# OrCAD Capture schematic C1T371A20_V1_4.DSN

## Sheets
1 000_Log: title: TELINK; rev: V1.4; note: C1T371A20
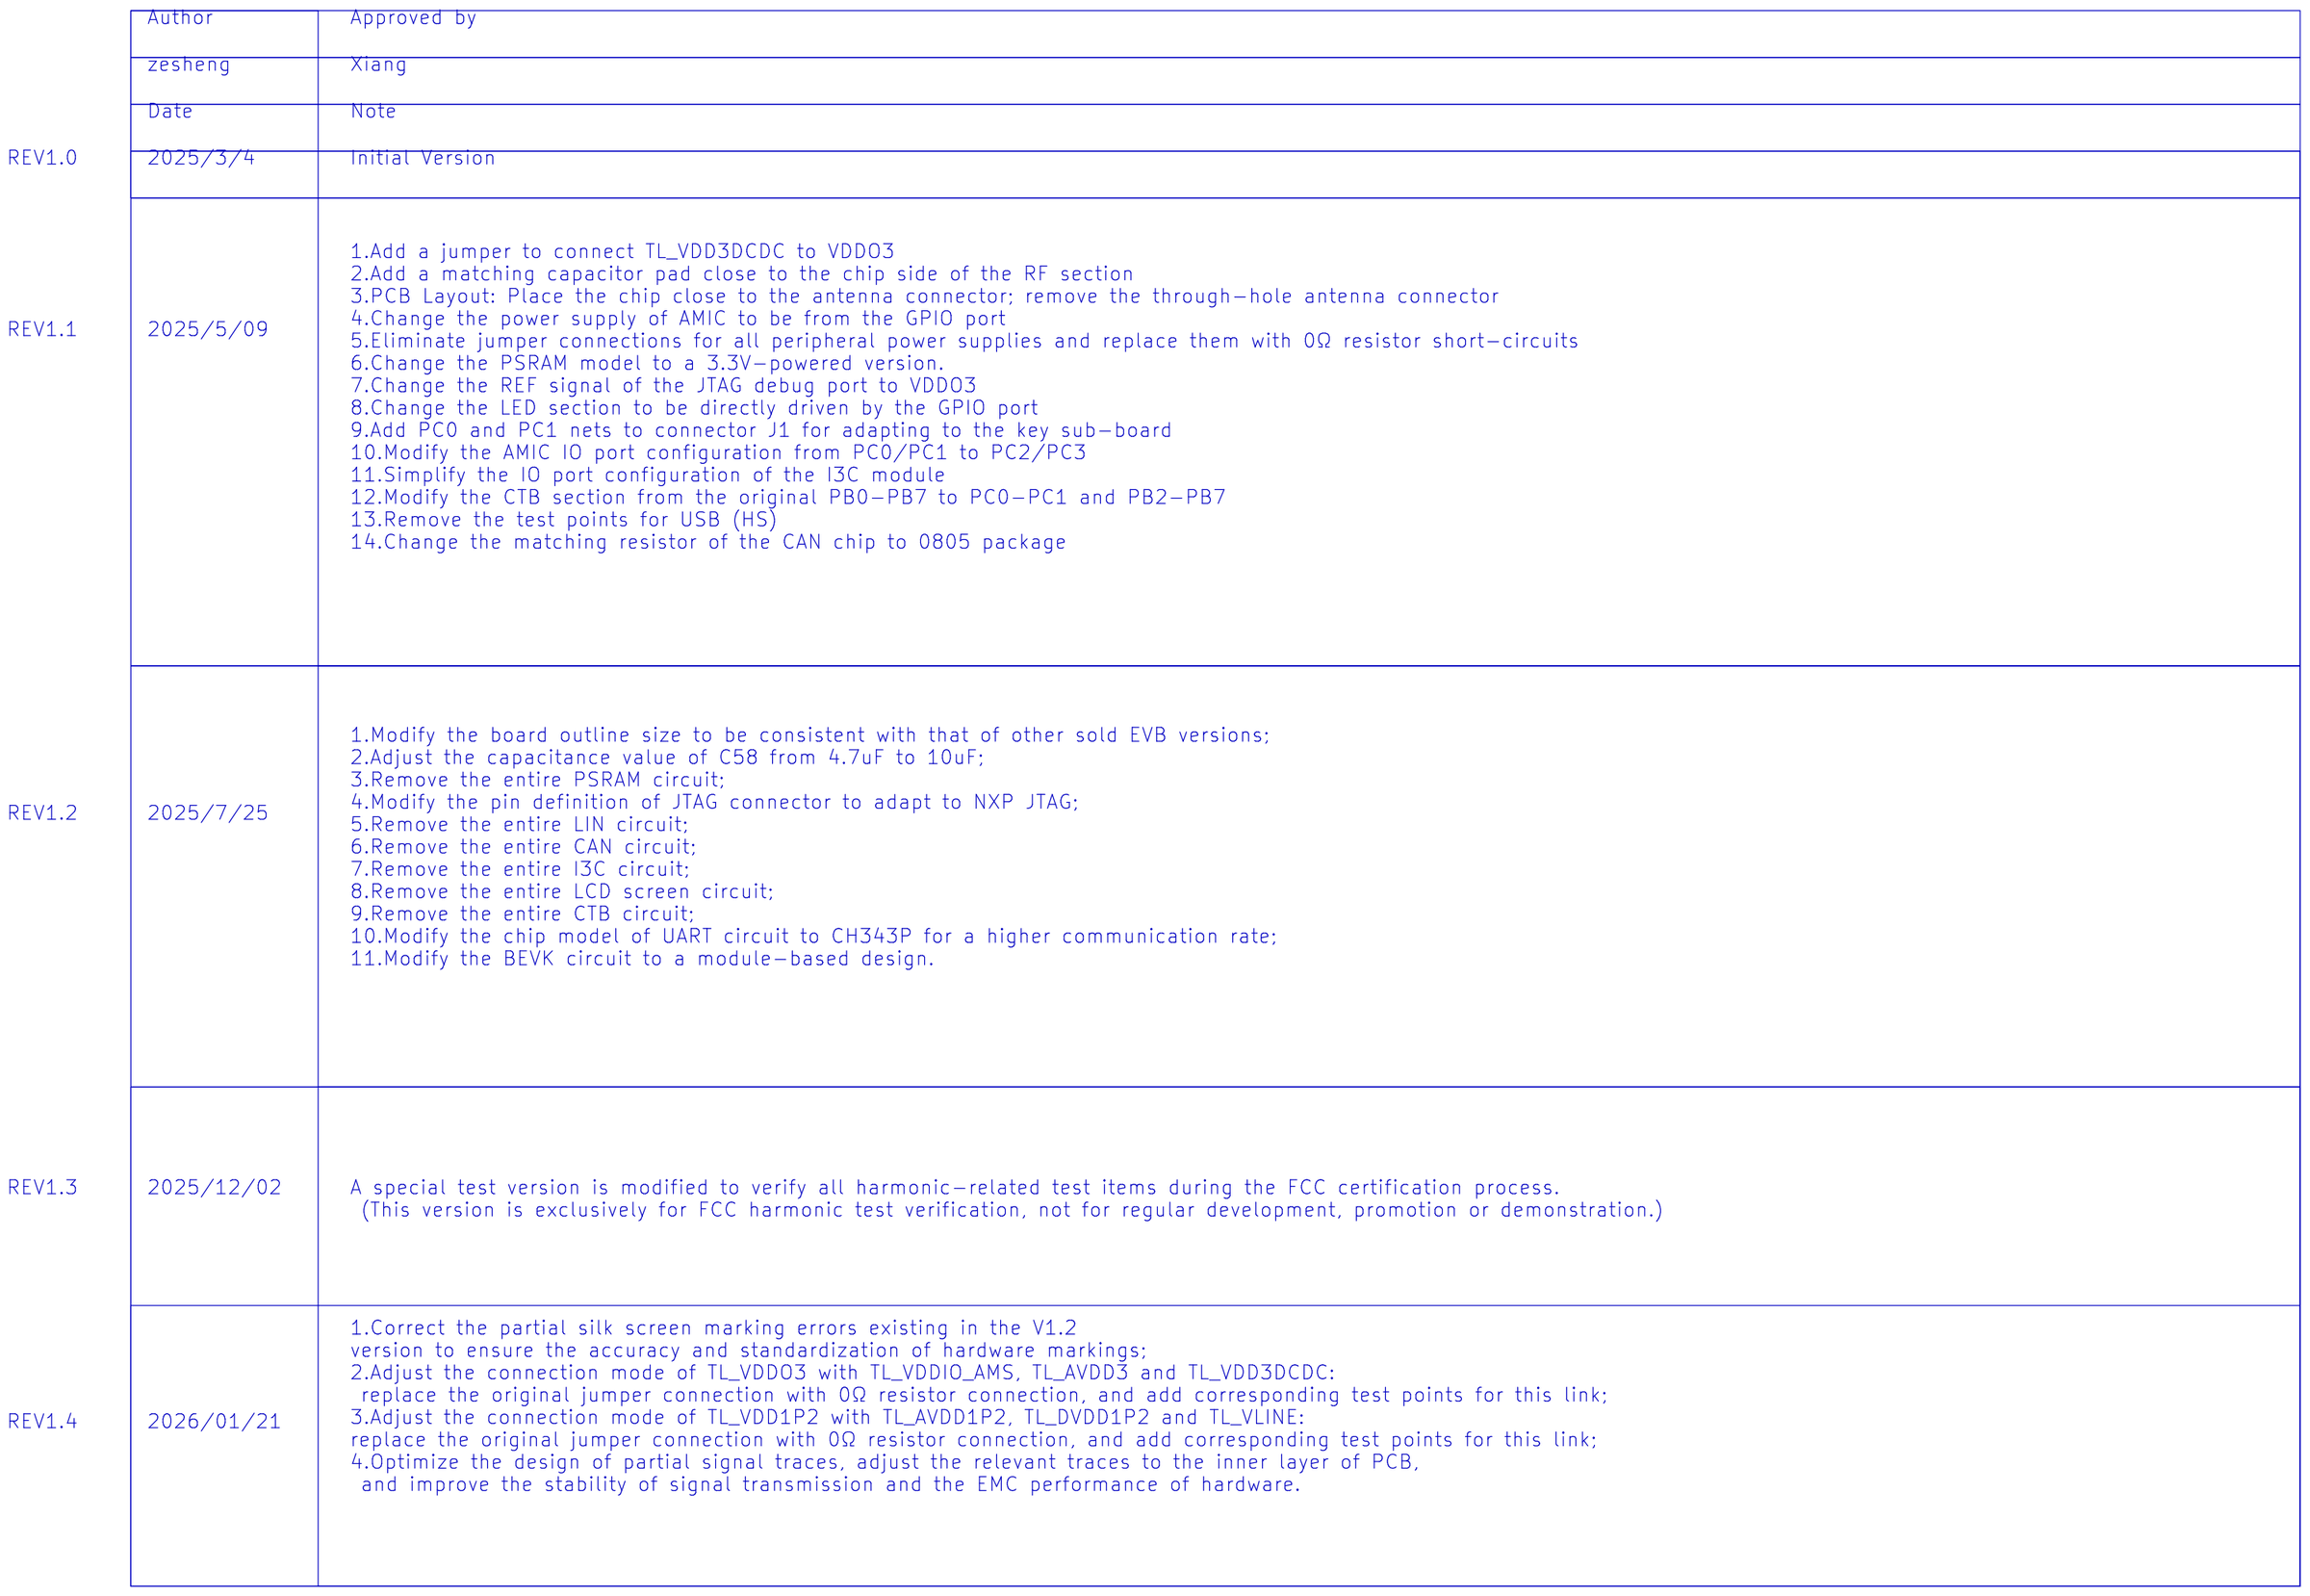
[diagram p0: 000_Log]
2 001_MAIN: size A3
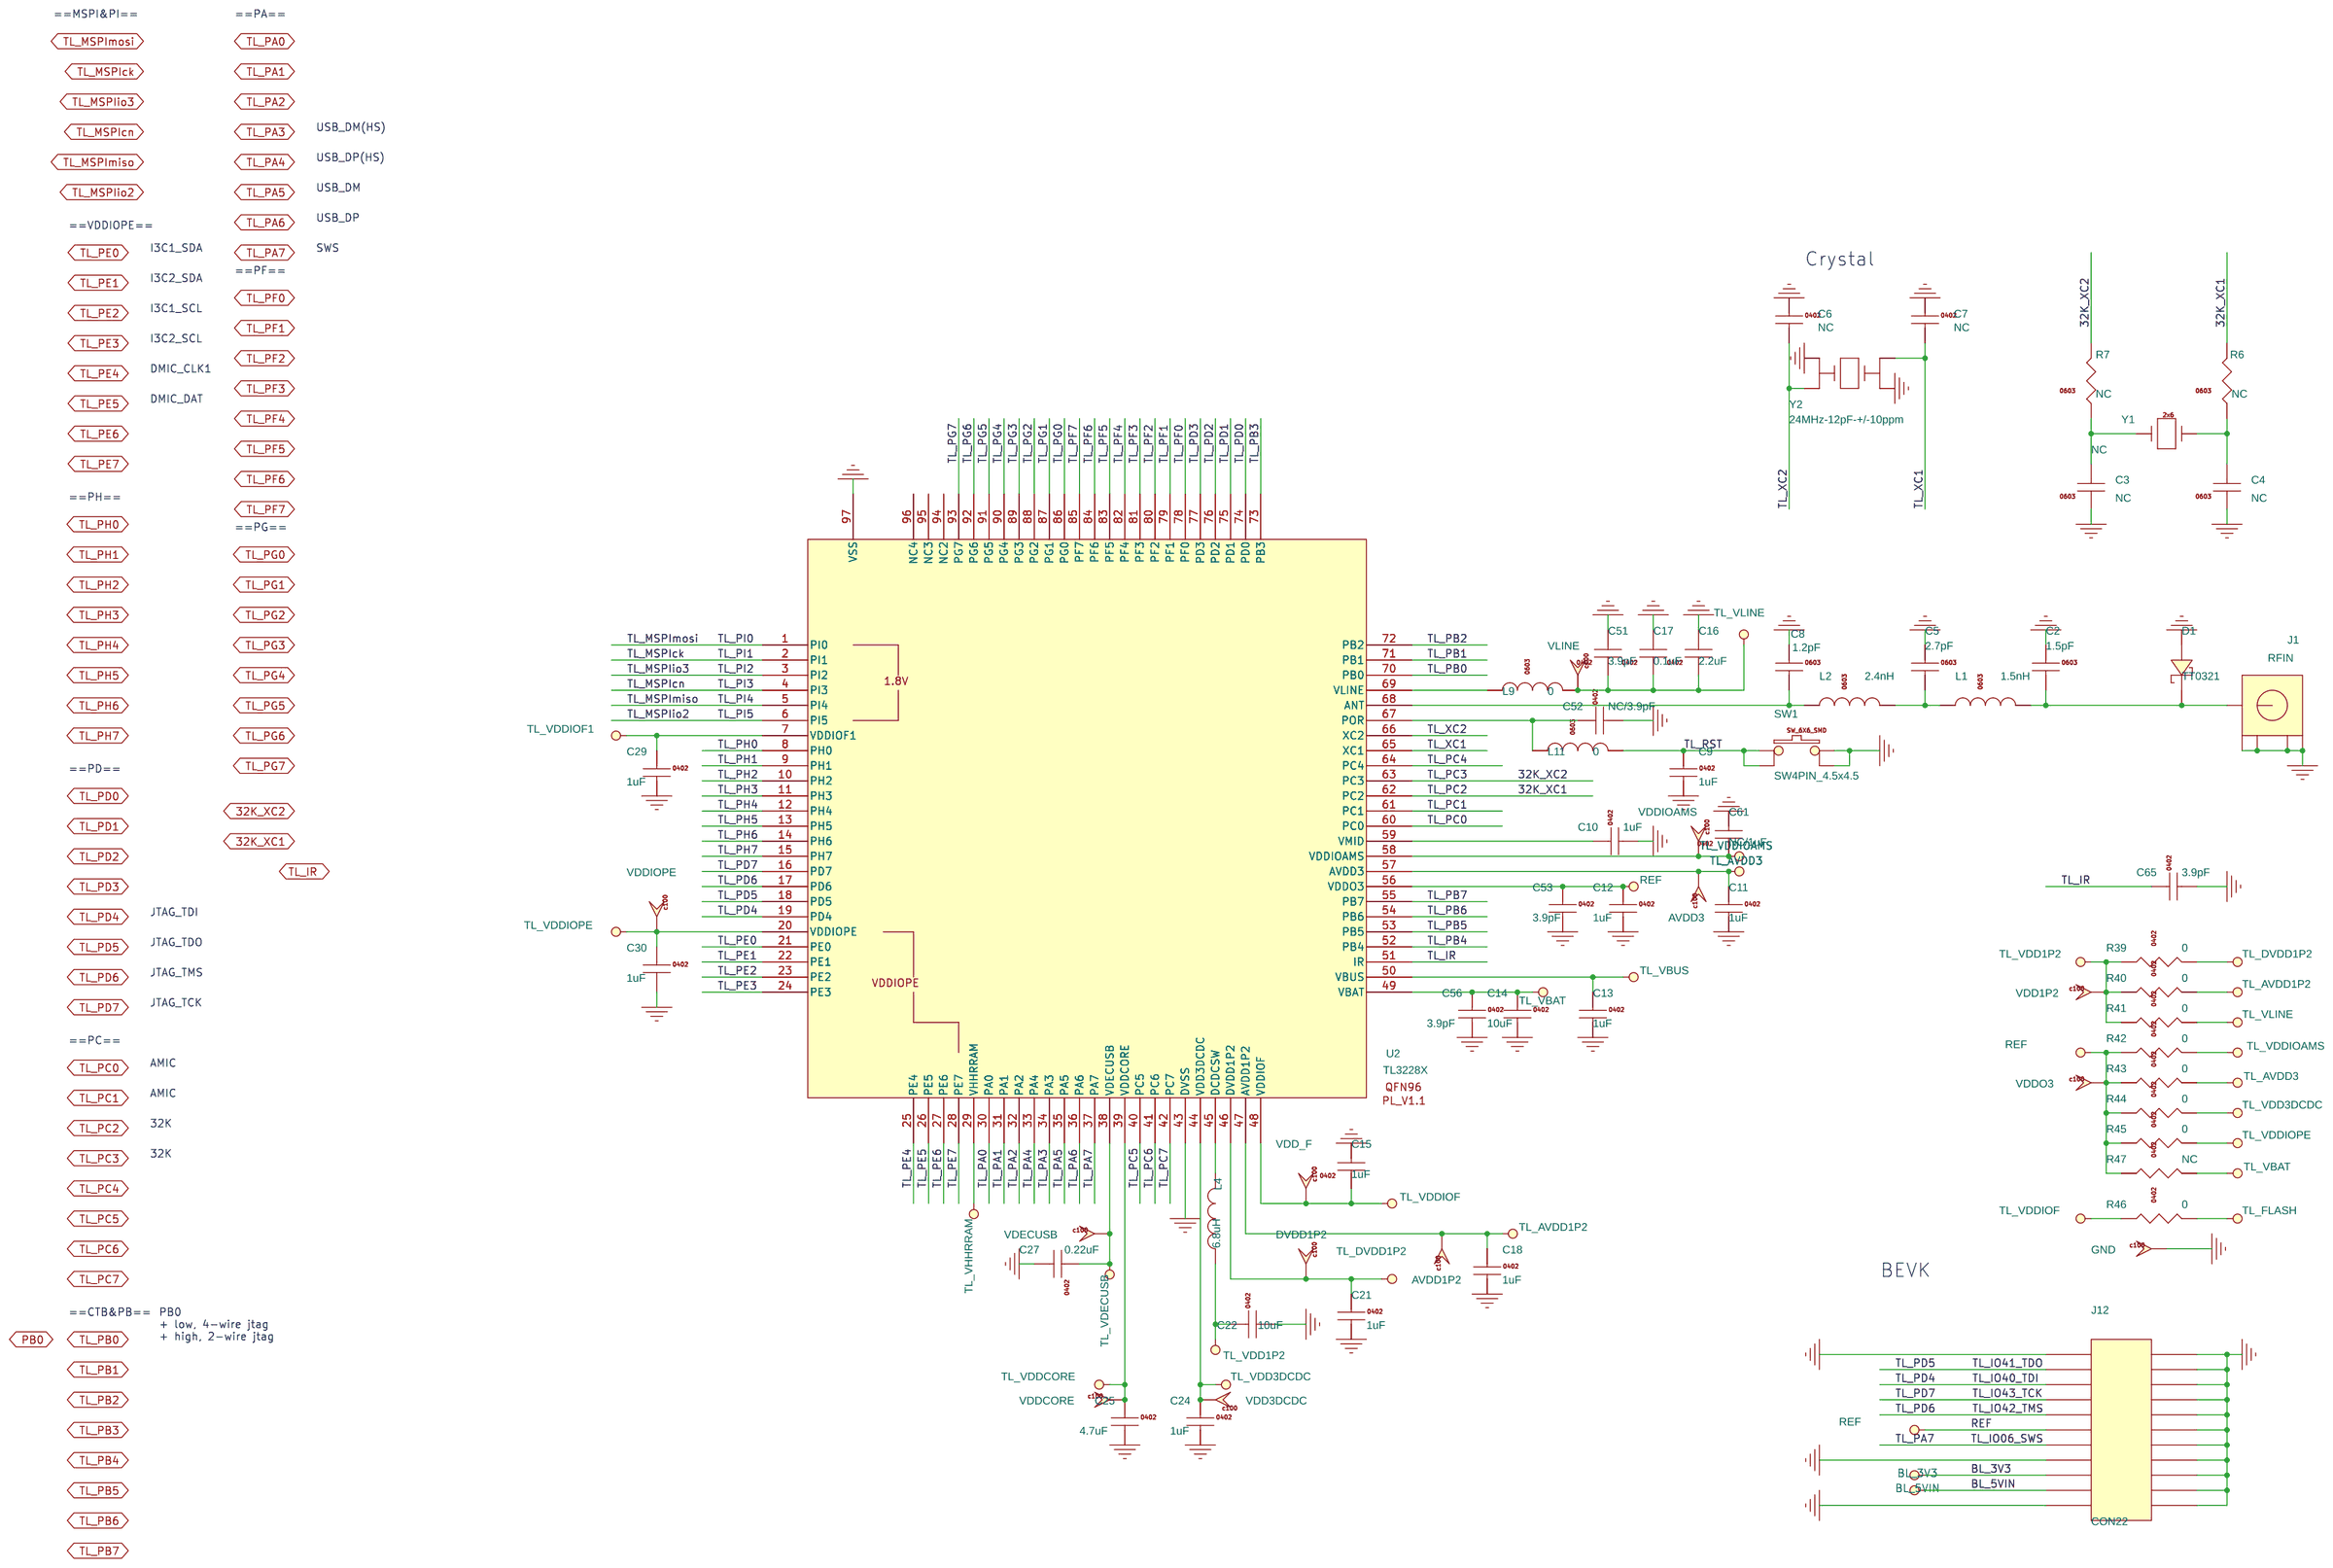
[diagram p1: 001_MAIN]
3 002_AUDIO: size A3
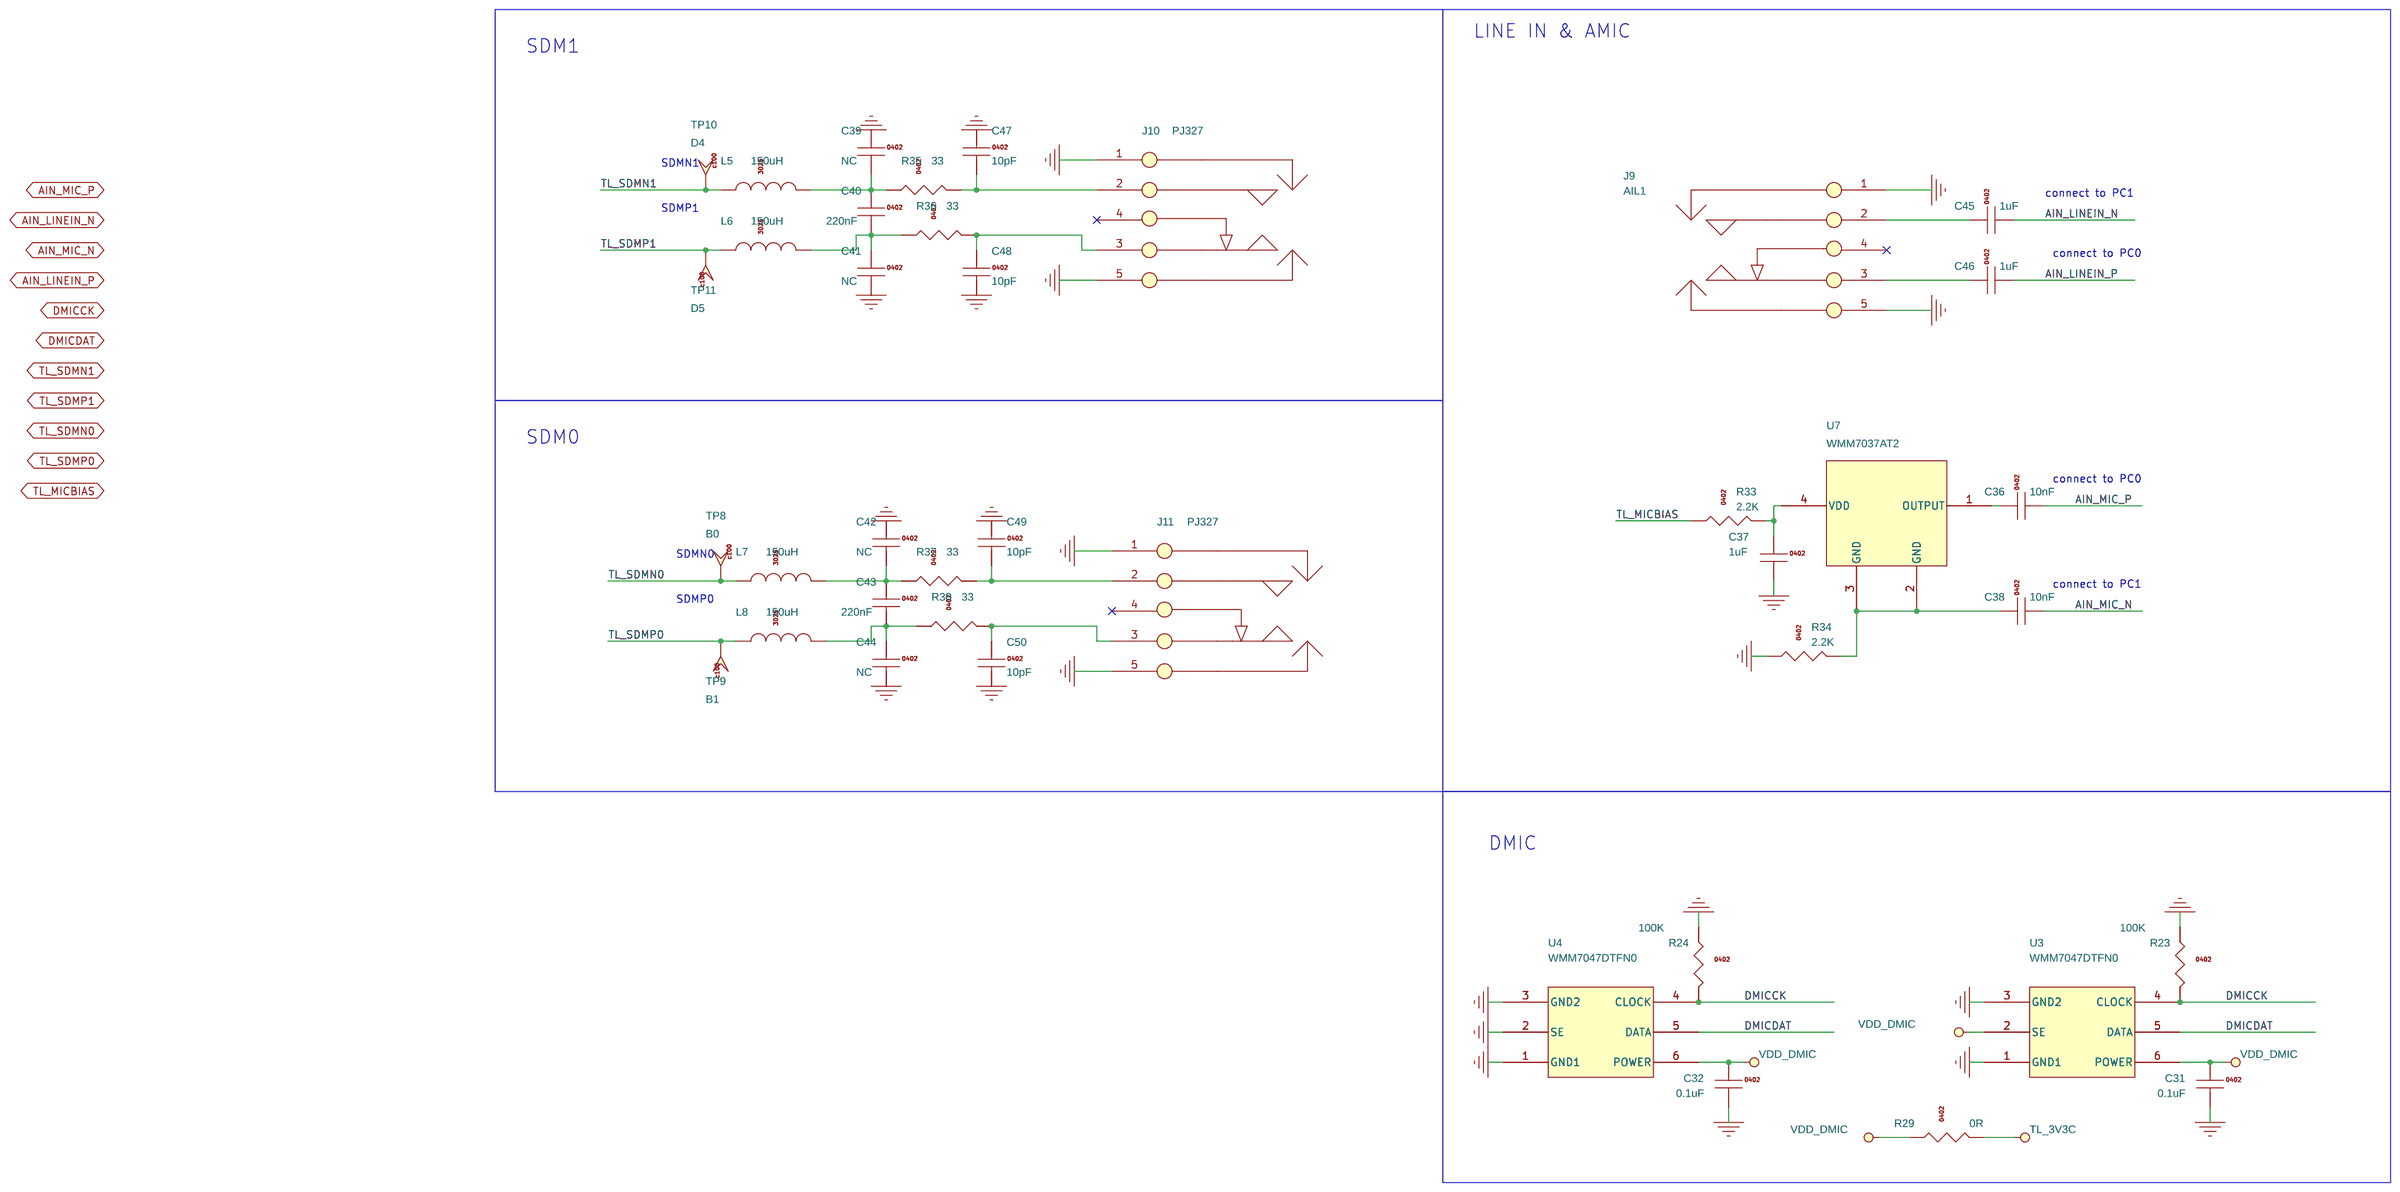
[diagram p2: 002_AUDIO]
4 003_INTERFACE1: size A3
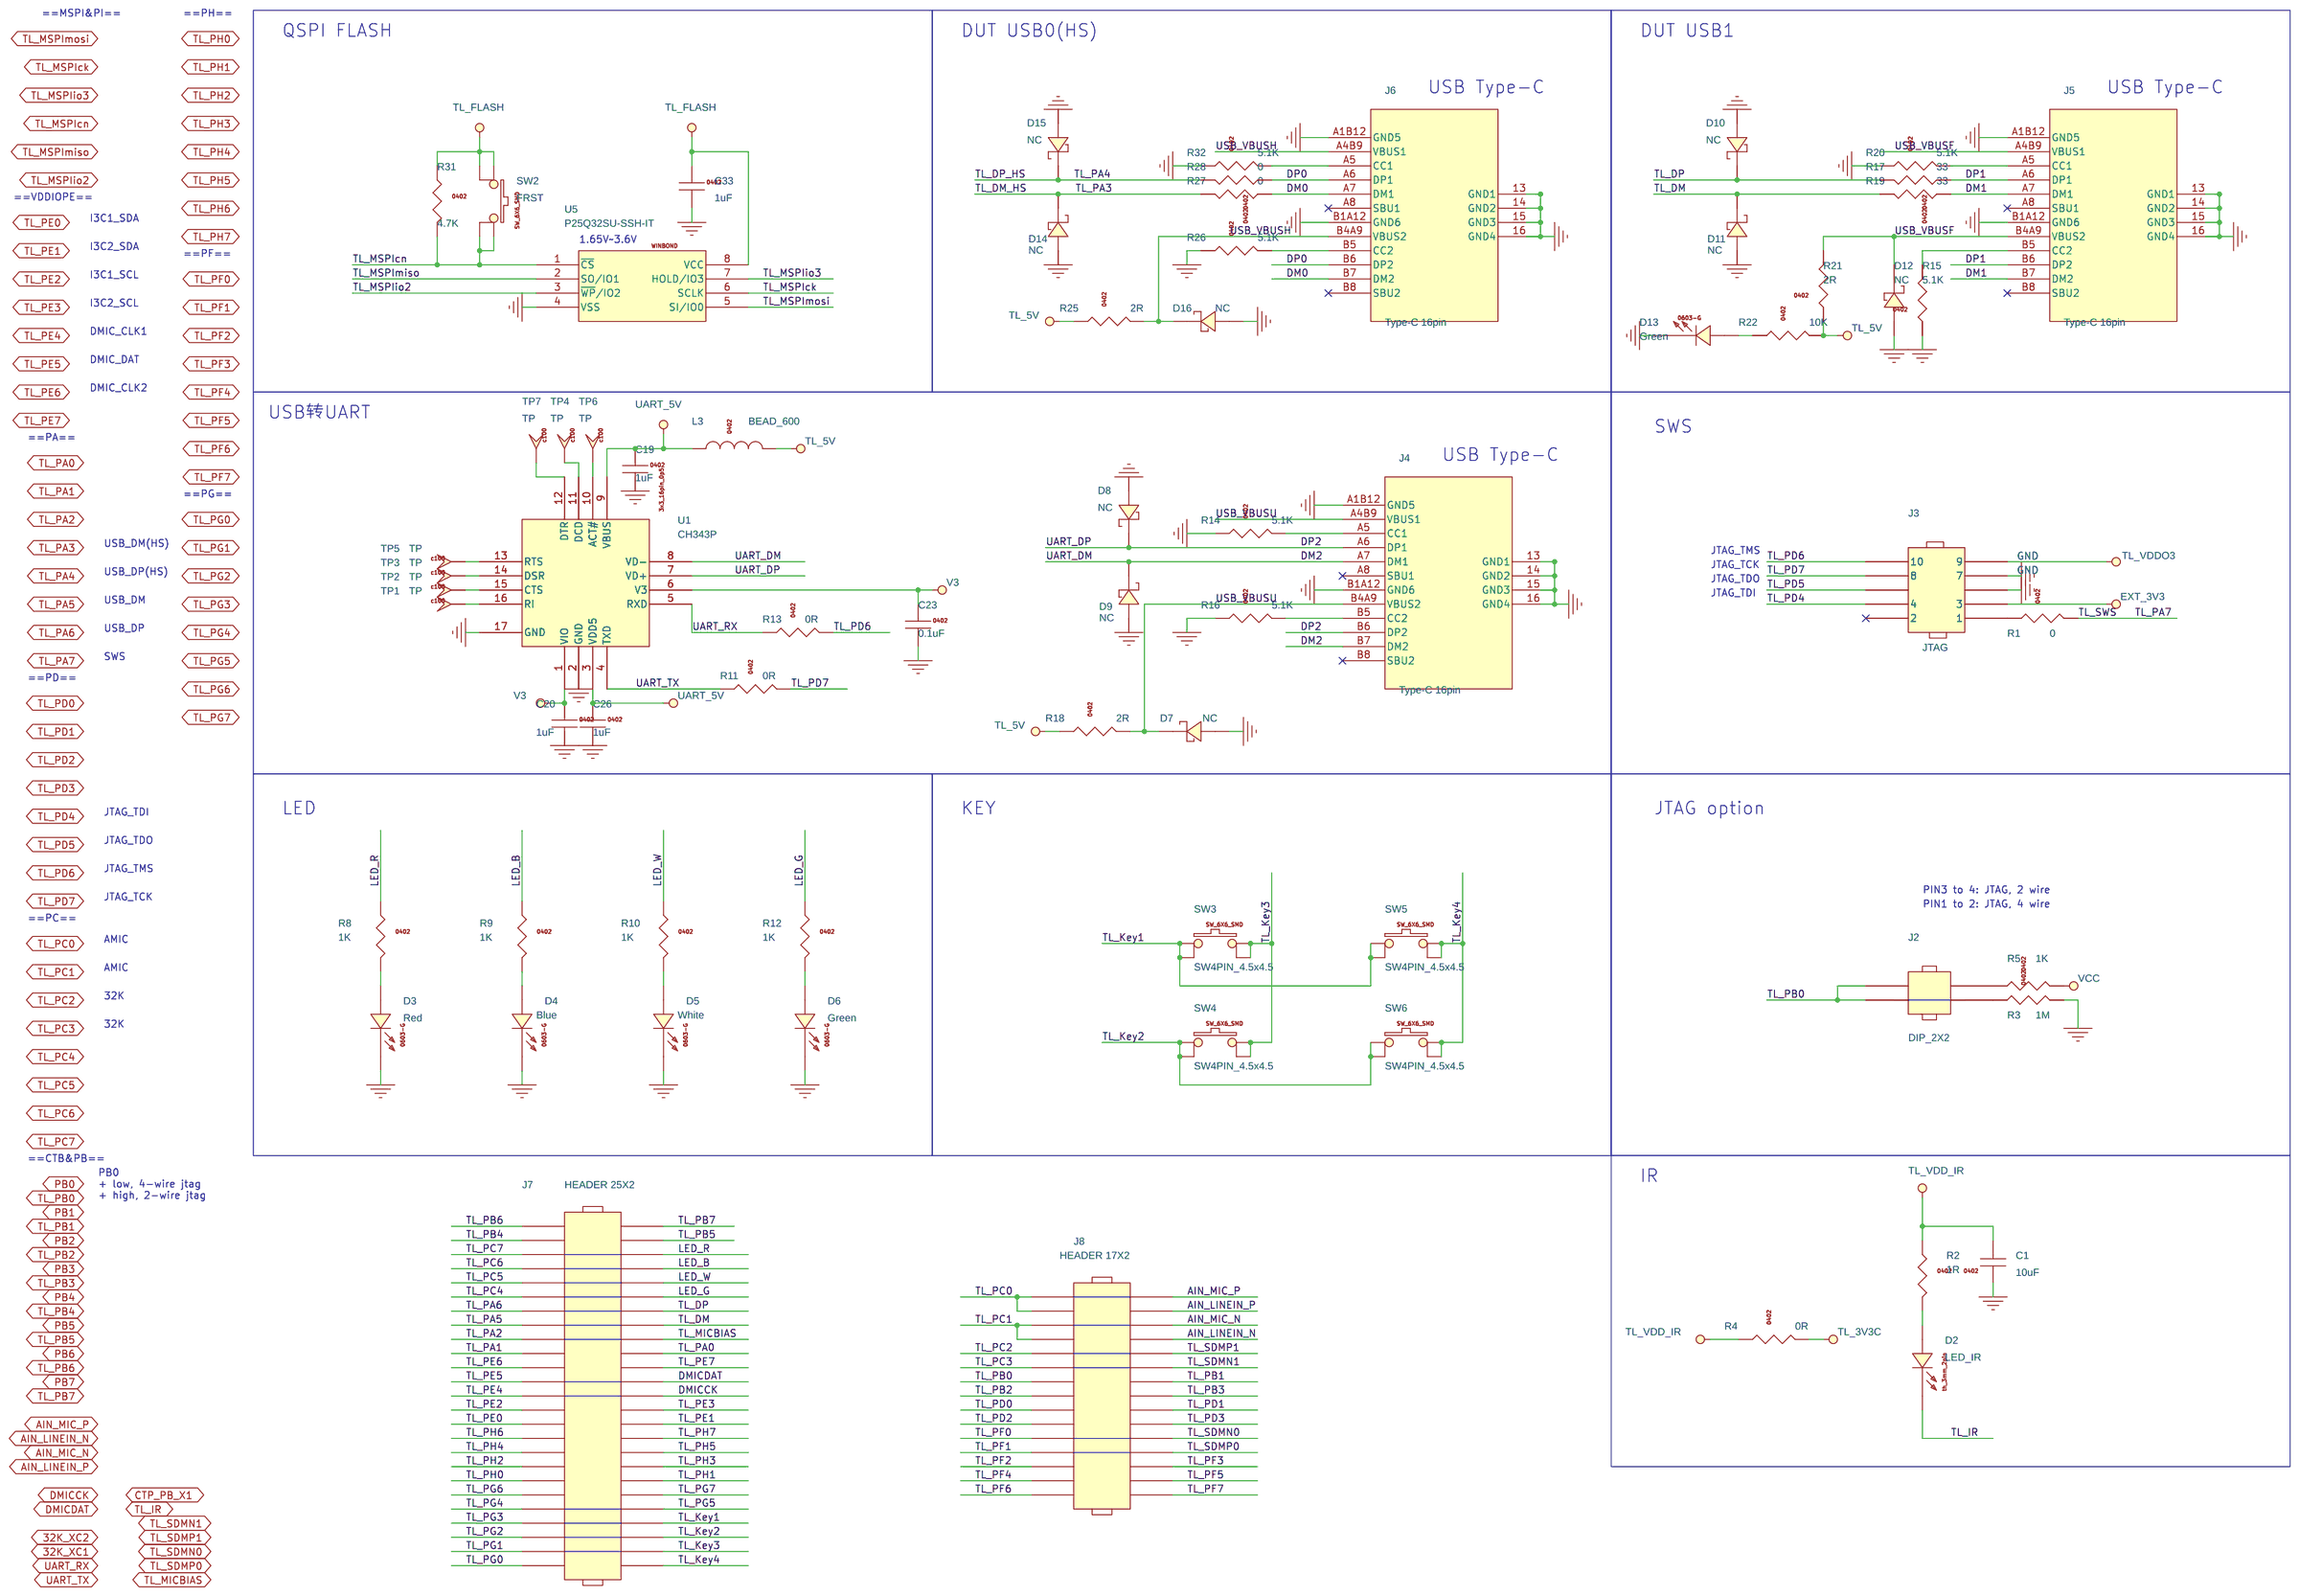
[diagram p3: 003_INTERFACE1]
5 004_PWR: size A4
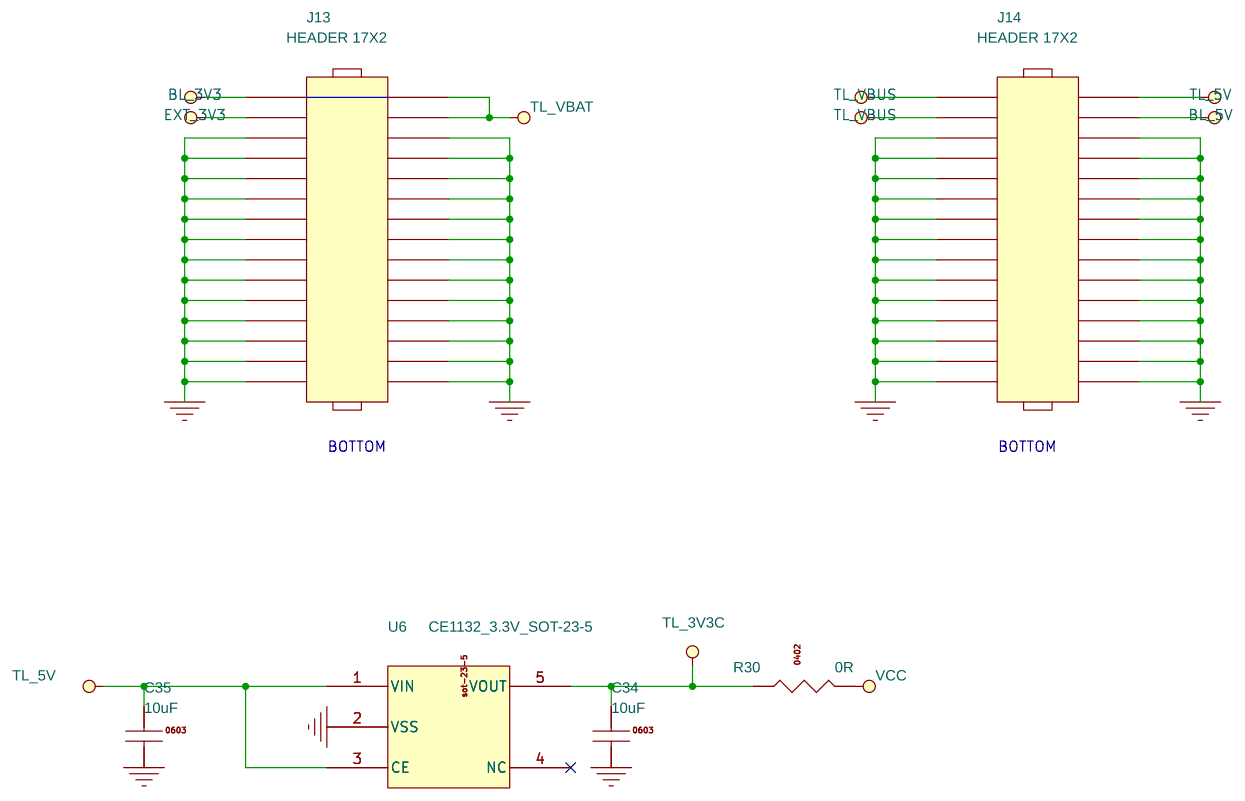
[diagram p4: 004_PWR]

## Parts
sheet 001_MAIN
AVDD1P2  TP  [TP100]
AVDD3  TP  [TP100]
C2  1.5pF  [0402]
C3  NC  [0402]
C4  NC  [0402]
C5  2.7pF  [0402]
C6  NC  [0402]
C7  NC  [0402]
C8  1.2pF  [0402]
C9  1uF  [0402]
C10  1uF  [0201]
C11  1uF  [0201]
C12  1uF  [0201]
C13  1uF  [0201]
C14  10uF  [0402]
C15  1uF  [0201]
C16  2.2uF  [0201]
C17  0.1uF  [0201]
C18  1uF  [0201]
C21  1uF  [0201]
C22  10uF  [0402]
C24  1uF  [0201]
C25  4.7uF  [0201]
C27  0.22uF  [0201]
C29  1uF  [0201]
C30  1uF  [0201]
C51  3.9pF  [0201]
C52  NC/3.9pF  [0201]
C53  3.9pF  [0201]
C56  3.9pF  [0201]
C61  NC/1uF  [0201]
C65  3.9pF  [0201]
D1  TT0321  [0402]
DVDD1P2  TP  [TP100]
GND  TP  [TP100]
J1  RFIN  [SMA-H]
J12  CON22  [ml_hdr254f-2x10x850]
L1  1.5nH  [0402]
L2  2.4nH  [0402]
L4  6.8uH  [0806L]
L9  0  [0201]
L11  0  [0201]
R6  NC  [0402]
R7  NC  [0402]
R39  0  [0402R]
R40  0  [0402R]
R41  0  [0402R]
R42  0  [0402R]
R43  0  [0402R]
R44  0  [0402R]
R45  0  [0402R]
R46  0  [0402R]
R47  NC  [0402R]
SW1  SW4PIN_4.5x4.5  [SW_6X6_SMD]
U2  TL3228X  [qfn_10x10_96pin_0p35_5p7x5p7]
VDD1P2  TP  [TP100]
VDD3DCDC  TP  [TP100]
VDD_F  TP  [TP100]
VDDCORE  TP  [TP100]
VDDIOAMS  TP  [TP100]
VDDIOPE  TP  [TP100]
VDDO3  TP  [TP100]
VDECUSB  TP  [TP100]
VLINE  TP  [TP100]
Y1  NC  [OSC-ABS07]
Y2  24MHz-12pF-+/-10ppm  [OSCCC250X320X110]
sheet 002_AUDIO
C31  0.1uF  [0402]
C32  0.1uF  [0402]
C36  10nF  [0402]
C37  1uF  [0402]
C38  10nF  [0402]
C39  NC  [0402]
C40  220nF  [0402]
C41  NC  [0402]
C42  NC  [0402]
C43  220nF  [0402]
C44  NC  [0402]
C45  1uF  [0402]
C46  1uF  [0402]
C47  10pF  [0402]
C48  10pF  [0402]
C49  10pF  [0402]
C50  10pF  [0402]
J9  AIL1  [PJ-327]
J10  PJ327  [PJ-327]
J11  PJ327  [PJ-327]
L5  150uH  [INDM3025X25]
L6  150uH  [INDM3025X25]
L7  150uH  [INDM3025X25]
L8  150uH  [INDM3025X25]
R23  100K  [0402]
R24  100K  [0402]
R29  0R  [0603r]
R33  2.2K  [0402]
R34  2.2K  [0402]
R35  33  [0402R]
R36  33  [0402R]
R37  33  [0402R]
R38  33  [0402R]
TP8  B0  [TP100]
TP9  B1  [TP100]
TP10  D4  [TP100]
TP11  D5  [TP100]
U3  WMM7047DTFN0  [DMIC_SPM0423HM4H-WB]
U4  WMM7047DTFN0  [DMIC_SPM0423HM4H-WB]
U7  WMM7037AT2  [ga_bfa423_a83]
sheet 003_INTERFACE1
C1  10uF  [0603C]
C19  1uF  [0402]
C20  1uF  [0402]
C23  0.1uF  [0402]
C26  1uF  [0402]
C33  1uF  [0402]
D2  LED_IR  [led_th_2p54mm_2pin]
D3  Red  [0603-LED]
D4  Blue  [0603-LED]
D5  White  [0603-LED]
D6  Green  [0603-LED]
D7  NC  [0402]
D8  NC  [0201]
D9  NC  [0201]
D10  NC  [0201]
D11  NC  [0201]
D12  NC  [0402]
D13  Green  [0603-LED]
D14  NC  [0201]
D15  NC  [0201]
D16  NC  [0402]
J2  DIP_2X2  [DipSwitch_2p54_7p62_2x2]
J3  JTAG  [HDR254F-2X5X850]
J4  Type-C 16pin  [type_c_cq_105pwb]
J5  Type-C 16pin  [type_c_cq_105pwb]
J6  Type-C 16pin  [type_c_cq_105pwb]
J7  HEADER 25X2  [hdr2x25-2r54-sm-m]
J8  HEADER 17X2  [SMD254M-2X15_RX1_30Y2_40]
L3  BEAD_600  [0402]
R1  0  [0402]
R2  1R  [0402]
R3  1M  [0402]
R4  0R  [0603r]
R5  1K  [0402]
R8  1K  [0402]
R9  1K  [0402]
R10  1K  [0402]
R11  0R  [0402]
R12  1K  [0402]
R13  0R  [0402]
R14  5.1K  [0402]
R15  5.1K  [0402]
R16  5.1K  [0402]
R17  33  [0402]
R18  2R  [0402]
R19  33  [0402]
R20  5.1K  [0402]
R21  2R  [0402]
R22  10K  [0402]
R25  2R  [0402]
R26  5.1K  [0402]
R27  0  [0402]
R28  0  [0402]
R31  4.7K  [0402]
R32  5.1K  [0402]
SW2  FRST  [SW_6X6_SMD]
SW3  SW4PIN_4.5x4.5  [SW_6X6_SMD]
SW4  SW4PIN_4.5x4.5  [SW_6X6_SMD]
SW5  SW4PIN_4.5x4.5  [SW_6X6_SMD]
SW6  SW4PIN_4.5x4.5  [SW_6X6_SMD]
TP1  TP  [TP100]
TP2  TP  [TP100]
TP3  TP  [TP100]
TP4  TP  [TP100]
TP5  TP  [TP100]
TP6  TP  [TP100]
TP7  TP  [TP100]
U1  CH343P  [qfn_3x3_16pin_0p5_1p70x1p70]
U5  P25Q32SU-SSH-IT  [W25X10_20_40BL]
sheet 004_PWR
C34  10uF  [0603C]
C35  10uF  [0603C]
J13  HEADER 17X2  [SMD254M-2X15_RX1_30Y2_40]
J14  HEADER 17X2  [SMD254M-2X15_RX1_30Y2_40]
R30  0R  [0603r]
U6  CE1132_3.3V_SOT-23-5  [sot-23-5]

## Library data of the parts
AVDD1P2 AVDD3 DVDD1P2 GND TP1-TP11 VDD1P2 VDD3DCDC VDD_F VDDCORE VDDIOAMS VDDIOPE VDDO3 VDECUSB VLINE = TestPad100
C2-C5 C8 = C1608_NC
C6 C7 C19 C20 C23 C26 C39 C41 C42 C44 = C1005_NC
C1 C9-C18 C21 C22 C24 C25 C27 C29 C30 C33 C36-C38 C45 C46 C51-C53 C56 C61 C65 = C1005X5R1C104K
D1 D7-D12 D14-D16 = DIODE_SCHOTTKY_0
J1 = SMA_JACK_2: PART: RF
J12 = CON24B_0
L1 L2 L9 L11 = MLK1608_000R
L4 = IND
R6 R7 = RS0603K102JT
R35-R47 = RS0402K330JT
SW1 SW3-SW6 = SW_6X6_SMD_0
U2 = TL3228X_QFN96
Y1 = OSC_2x6_2pin_16Mhz
Y2 = CRYSTAL4_SM_0
C31 C32 = C1005X5R1C104K_1
C40 C43 = C1005X5R1C224M
C47-C50 = C1005C0G1H100D
J9-J11 = PJ327_2
L5-L8 = IND_150uH_3025
R1 R3-R5 R23 R24 R29-R31 R33 R34 = RS0402K104JT
U3 = LD1117_SO_1
U4 = LD1117_SO_0
U7 = MULPS4CX-RM5_0
D2 = Led_Th_3mm_1
D3-D6 D13 = 0603D_Green
J2 = HEADER_2X2_0
J3 = CONN_PLUG_5x2
J4-J6 = Type-C_16pin_0
J7 = HEADER_16X2_9
J8 J13 J14 = HEADER_16X2_13
L3 = MMZ1005Y601C
R2 R11 R13 R22 = RS0402K102JT
R8-R10 R12 = RS0402K101JT
R14-R21 R25-R28 R32 = RS0402K330JT: ROOM: USB
SW2 = SW_6X6_SMD
U1 = CH343P
U5 = GD25LD40C_0
C34 C35 = C1608X5R0J106M
U6 = CE1132_1V8_SOT-23-5

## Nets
GND: C1.1 C2.1 C3.1 C4.1 C5.1 C6.1 C7.1 C8.1 C9.2 C10.2 C11.2 C12.2 C13.2 C14.2 C15.2 C16.2 C17.2 C18.2 C19.2 C20.2 C21.2 C22.2 C23.2 C24.2 C25.2 C26.2 C27.2 C29.2 C30.2 C31.2 C32.2 C33.2 C34.2 C35.2 C37.2 C39.1 C41.2 C42.1 C44.2 C47.1 C48.2 C49.1 C50.2 C51.2 C52.2 C53.2 C56.2 C61.2 C65.2 D1.1(ANODE) D3.C(CATHODE) D4.C(CATHODE) D5.C(CATHODE) D6.C(CATHODE) D7.1(ANODE) D8.1(ANODE) D9.1(ANODE) D10.1(ANODE) D11.1(ANODE) D12.1(ANODE) D13.C(CATHODE) D14.1(ANODE) D15.1(ANODE) D16.1(ANODE) GND.1(TP) J1.2 J1.3 J1.4 J1.5 J3.3(7) J3.5 J4.13(GND1) J4.14(GND2) J4.15(GND3) J4.16(GND4) J4.A1B12(GND5) J4.B1A12(GND6) J5.13(GND1) J5.14(GND2) J5.15(GND3) J5.16(GND4) J5.A1B12(GND5) J5.B1A12(GND6) J6.13(GND1) J6.14(GND2) J6.15(GND3) J6.16(GND4) J6.A1B12(GND5) J6.B1A12(GND6) J9.1 J9.5 J10.1 J10.5 J11.1 J11.5 J12.1 J12.8 J12.11 J12.12 J12.13 J12.14 J12.15 J12.16 J12.17 J12.18 J12.19 J12.20 J12.21 J12.22 J13.5 J13.6 J13.7 J13.8 J13.9 J13.10 J13.11 J13.12 J13.13 J13.14 J13.15 J13.16 J13.17 J13.18 J13.19 J13.20 J13.21 J13.22 J13.23 J13.24 J13.25 J13.26 J13.27 J13.28 J13.29 J13.30 J14.5 J14.6 J14.7 J14.8 J14.9 J14.10 J14.11 J14.12 J14.13 J14.14 J14.15 J14.16 J14.17 J14.18 J14.19 J14.20 J14.21 J14.22 J14.23 J14.24 J14.25 J14.26 J14.27 J14.28 J14.29 J14.30 R3.2 R14.1 R15.1 R16.1 R20.1 R23.1 R24.1 R26.1 R32.1 R34.1 SW1.3 SW1.4 U1.2(GND) U1.17(GND) U2.43(DVSS) U2.97(VSS) U3.1(GND1) U3.3(GND2) U4.1(GND1) U4.2(SE) U4.3(GND2) U5.4(VSS) U6.2(VSS) Y2.2 Y2.4
V3: C20.1 C23.1 U1.1(VIO) U1.6(V3)
VDD_DMIC: C31.1 C32.1 R29.1 U3.2(SE) U3.6(POWER) U4.6(POWER)
32K_XC1: R6.2 U2.62(PC2)
32K_XC2: R7.2 U2.63(PC3)
AIN_LINEIN_N: C45.2
AIN_LINEIN_N (page 003_INTERFACE1): J8.7
AIN_LINEIN_P: C46.2
AIN_LINEIN_P (page 003_INTERFACE1): J8.3
AIN_MIC_N: C38.2
AIN_MIC_N (page 003_INTERFACE1): J8.5
AIN_MIC_P: C36.2
AIN_MIC_P (page 003_INTERFACE1): J8.1
BL_3V3: J12.9 J13.2
BL_5V: J12.10 J14.3
DM0: J6.A7(DM1) J6.B7(DM2) R27.1
DM1: J5.A7(DM1) J5.B7(DM2) R19.1
DM2: D9.2(CATHODE) J4.A7(DM1) J4.B7(DM2) U1.8(VD-)
DMICCK: R23.2 R24.2 U3.4(CLOCK) U4.4(CLOCK)
DMICCK (page 003_INTERFACE1): J7.25
DMICDAT: U3.5(DATA) U4.5(DATA)
DMICDAT (page 003_INTERFACE1): J7.23
DP0: J6.A6(DP1) J6.B6(DP2) R28.1
DP1: J5.A6(DP1) J5.B6(DP2) R17.1
DP2: D8.2(CATHODE) J4.A6(DP1) J4.B6(DP2) U1.7(VD+)
EXT_3V3: J3.7(3) J13.4 R30.2
LED_B: J7.7 R9.1
LED_G: J7.11 R12.1
LED_R: J7.5 R8.1
LED_W: J7.9 R10.1
TL_3V3C: C34.1 R4.2 R29.2 R30.1 U6.5(VOUT)
TL_5V: C35.1 J14.1 L3.2 R18.1 R21.1 R22.2 R25.1 U6.1(VIN) U6.3(CE)
TL_AVDD1P2: AVDD1P2.1(TP) C18.1 R40.2 U2.47(AVDD1P2)
TL_AVDD3: AVDD3.1(TP) C11.1 R43.2 U2.57(AVDD3)
TL_DM: D11.2(CATHODE) J7.15 R19.2
TL_DP: D10.2(CATHODE) J7.13 R17.2
TL_DVDD1P2: C21.1 DVDD1P2.1(TP) R39.2 U2.46(DVDD1P2)
TL_FLASH: C33.1 R31.1 R46.2 SW2.1 SW2.2 U5.8(VCC)
TL_IR: C65.1 U2.51(IR)
TL_IR (page 003_INTERFACE1): D2.C(CATHODE)
TL_Key1: J7.43 SW3.1 SW3.2 SW5.1 SW5.2
TL_Key2: J7.45 SW4.1 SW4.2 SW6.1 SW6.2
TL_Key3: J7.47 SW3.3 SW3.4 SW4.3 SW4.4
TL_Key4: J7.49 SW5.3 SW5.4 SW6.3 SW6.4
TL_MICBIAS: R33.1
TL_MICBIAS (page 003_INTERFACE1): J7.17
TL_MSPIck: U2.2(PI1)
TL_MSPIck (page 003_INTERFACE1): U5.6(SCLK)
TL_MSPIcn: U2.4(PI3)
TL_MSPIcn (page 003_INTERFACE1): R31.2 SW2.3 SW2.4 U5.1(~{CS})
TL_MSPIio2: U2.6(PI5)
TL_MSPIio2 (page 003_INTERFACE1): U5.3(~{WP}/IO2)
TL_MSPIio3: U2.3(PI2)
TL_MSPIio3 (page 003_INTERFACE1): U5.7(HOLD/IO3)
TL_MSPImiso: U2.5(PI4)
TL_MSPImiso (page 003_INTERFACE1): U5.2(SO/IO1)
TL_MSPImosi: U2.1(PI0)
TL_MSPImosi (page 003_INTERFACE1): U5.5(SI/IO0)
TL_PA0: U2.30(PA0)
TL_PA0 (page 003_INTERFACE1): J7.19
TL_PA1: U2.31(PA1)
TL_PA1 (page 003_INTERFACE1): J7.20
TL_PA2: U2.32(PA2)
TL_PA2 (page 003_INTERFACE1): J7.18
TL_PA3: U2.34(PA3)
TL_PA3 (page 003_INTERFACE1): D14.2(CATHODE) R27.2
TL_PA4: U2.33(PA4)
TL_PA4 (page 003_INTERFACE1): D15.2(CATHODE) R28.2
TL_PA5: U2.35(PA5)
TL_PA5 (page 003_INTERFACE1): J7.16
TL_PA6: U2.36(PA6)
TL_PA6 (page 003_INTERFACE1): J7.14
TL_PA7: J12.7 U2.37(PA7)
TL_PA7 (page 003_INTERFACE1): R1.2
TL_PB0: U2.70(PB0)
TL_PB0 (page 003_INTERFACE1): J2.1 J2.3 J8.14
TL_PB1: U2.71(PB1)
TL_PB1 (page 003_INTERFACE1): J8.13
TL_PB2: U2.72(PB2)
TL_PB2 (page 003_INTERFACE1): J8.16
TL_PB3: U2.73(PB3)
TL_PB3 (page 003_INTERFACE1): J8.15
TL_PB4: U2.52(PB4)
TL_PB4 (page 003_INTERFACE1): J7.4
TL_PB5: U2.53(PB5)
TL_PB5 (page 003_INTERFACE1): J7.3
TL_PB6: U2.54(PB6)
TL_PB6 (page 003_INTERFACE1): J7.2
TL_PB7: U2.55(PB7)
TL_PB7 (page 003_INTERFACE1): J7.1
TL_PC0: U2.60(PC0)
TL_PC0 (page 003_INTERFACE1): J8.2 J8.4
TL_PC1: U2.61(PC1)
TL_PC1 (page 003_INTERFACE1): J8.6 J8.8
TL_PC2: J8.10
TL_PC3: J8.12
TL_PC4: U2.64(PC4)
TL_PC4 (page 003_INTERFACE1): J7.12
TL_PC5: U2.40(PC5)
TL_PC5 (page 003_INTERFACE1): J7.10
TL_PC6: U2.41(PC6)
TL_PC6 (page 003_INTERFACE1): J7.8
TL_PC7: U2.42(PC7)
TL_PC7 (page 003_INTERFACE1): J7.6
TL_PD0: U2.74(PD0)
TL_PD0 (page 003_INTERFACE1): J8.18
TL_PD1: U2.75(PD1)
TL_PD1 (page 003_INTERFACE1): J8.17
TL_PD2: U2.76(PD2)
TL_PD2 (page 003_INTERFACE1): J8.20
TL_PD3: U2.77(PD3)
TL_PD3 (page 003_INTERFACE1): J8.19
TL_PD4: J12.3 U2.19(PD4)
TL_PD4 (page 003_INTERFACE1): J3.8(4)
TL_PD5: J12.2 U2.18(PD5)
TL_PD5 (page 003_INTERFACE1): J3.6
TL_PD6: J12.5 U2.17(PD6)
TL_PD6 (page 003_INTERFACE1): J3.2(10) R13.2
TL_PD7: J12.4 U2.16(PD7)
TL_PD7 (page 003_INTERFACE1): J3.4(8) R11.2
TL_PE0: U2.21(PE0)
TL_PE0 (page 003_INTERFACE1): J7.30
TL_PE1: U2.22(PE1)
TL_PE1 (page 003_INTERFACE1): J7.29
TL_PE2: U2.23(PE2)
TL_PE2 (page 003_INTERFACE1): J7.28
TL_PE3: U2.24(PE3)
TL_PE3 (page 003_INTERFACE1): J7.27
TL_PE4: U2.25(PE4)
TL_PE4 (page 003_INTERFACE1): J7.26
TL_PE5: U2.26(PE5)
TL_PE5 (page 003_INTERFACE1): J7.24
TL_PE6: U2.27(PE6)
TL_PE6 (page 003_INTERFACE1): J7.22
TL_PE7: U2.28(PE7)
TL_PE7 (page 003_INTERFACE1): J7.21
TL_PF0: U2.78(PF0)
TL_PF0 (page 003_INTERFACE1): J8.22
TL_PF1: U2.79(PF1)
TL_PF1 (page 003_INTERFACE1): J8.24
TL_PF2: U2.80(PF2)
TL_PF2 (page 003_INTERFACE1): J8.26
TL_PF3: U2.81(PF3)
TL_PF3 (page 003_INTERFACE1): J8.25
TL_PF4: U2.82(PF4)
TL_PF4 (page 003_INTERFACE1): J8.28
TL_PF5: U2.83(PF5)
TL_PF5 (page 003_INTERFACE1): J8.27
TL_PF6: U2.84(PF6)
TL_PF6 (page 003_INTERFACE1): J8.30
TL_PF7: U2.85(PF7)
TL_PF7 (page 003_INTERFACE1): J8.29
TL_PG0: U2.86(PG0)
TL_PG0 (page 003_INTERFACE1): J7.50
TL_PG1: U2.87(PG1)
TL_PG1 (page 003_INTERFACE1): J7.48
TL_PG2: U2.88(PG2)
TL_PG2 (page 003_INTERFACE1): J7.46
TL_PG3: U2.89(PG3)
TL_PG3 (page 003_INTERFACE1): J7.44
TL_PG4: U2.90(PG4)
TL_PG4 (page 003_INTERFACE1): J7.42
TL_PG5: U2.91(PG5)
TL_PG5 (page 003_INTERFACE1): J7.41
TL_PG6: U2.92(PG6)
TL_PG6 (page 003_INTERFACE1): J7.40
TL_PG7: U2.93(PG7)
TL_PG7 (page 003_INTERFACE1): J7.39
TL_PH0: U2.8(PH0)
TL_PH0 (page 003_INTERFACE1): J7.38
TL_PH1: U2.9(PH1)
TL_PH1 (page 003_INTERFACE1): J7.37
TL_PH2: U2.10(PH2)
TL_PH2 (page 003_INTERFACE1): J7.36
TL_PH3: U2.11(PH3)
TL_PH3 (page 003_INTERFACE1): J7.35
TL_PH4: U2.12(PH4)
TL_PH4 (page 003_INTERFACE1): J7.34
TL_PH5: U2.13(PH5)
TL_PH5 (page 003_INTERFACE1): J7.33
TL_PH6: U2.14(PH6)
TL_PH6 (page 003_INTERFACE1): J7.32
TL_PH7: U2.15(PH7)
TL_PH7 (page 003_INTERFACE1): J7.31
TL_RST: C9.1 L11.2 SW1.1 SW1.2
TL_SDMN0: L7.1 TP8.1(TP)
TL_SDMN0 (page 003_INTERFACE1): J8.21
TL_SDMN1: L5.1 TP10.1(TP)
TL_SDMN1 (page 003_INTERFACE1): J8.11
TL_SDMP0: L8.1 TP9.1(TP)
TL_SDMP0 (page 003_INTERFACE1): J8.23
TL_SDMP1: L6.1 TP11.1(TP)
TL_SDMP1 (page 003_INTERFACE1): J8.9
TL_VBAT: C14.1 C56.1 J13.1 J13.3 R47.2 U2.49(VBAT)
TL_VBUS: C13.1 J14.2 J14.4 U2.50(VBUS)
TL_VDD1P2: C22.1 L4.2 R39.1 R40.1 R41.1 VDD1P2.1(TP)
TL_VDD3DCDC: C24.1 R44.2 U2.44(VDD3DCDC) VDD3DCDC.1(TP)
TL_VDD_IR: C1.2 R2.1 R4.1
TL_VDDCORE: C25.1 U2.39(VDDCORE) VDDCORE.1(TP)
TL_VDDIOAMS: C61.1 R42.2 U2.58(VDDIOAMS) VDDIOAMS.1(TP)
TL_VDDIOF: C15.1 R46.1 U2.48(VDDIOF) VDD_F.1(TP)
TL_VDDIOF1: C29.1 U2.7(VDDIOF1)
TL_VDDIOPE: C30.1 R45.2 U2.20(VDDIOPE) VDDIOPE.1(TP)
TL_VDDO3: C12.1 C53.1 J3.1(9) J12.6 R5.2 R42.1 R43.1 R44.1 R45.1 R47.1 U2.56(VDDO3) VDDO3.1(TP)
TL_VDECUSB: C27.1 U2.38(VDECUSB) VDECUSB.1(TP)
TL_VHHRRAM: U2.29(VHHRRAM)
TL_VLINE: C16.1 C17.1 C51.1 L9.2 R41.2 VLINE.1(TP)
TL_XC1: C7.2 U2.65(XC1) Y2.1
TL_XC2: C6.2 U2.66(XC2) Y2.3
UART_5V: C19.1 C26.1 L3.1 U1.3(VDD5) U1.9(VBUS)
UART_RX: R13.1 U1.5(RXD)
UART_TX: R11.1 U1.4(TXD)
USB_VBUSF: D12.2(CATHODE) J5.A4B9(VBUS1) J5.B4A9(VBUS2) R21.2
USB_VBUSH: D16.2(CATHODE) J6.A4B9(VBUS1) J6.B4A9(VBUS2) R25.2
USB_VBUSU: D7.2(CATHODE) J4.A4B9(VBUS1) J4.B4A9(VBUS2) R18.2
N20198704: C5.2 L1.1 L2.2
N20202485: C3.2 R7.1 Y1.1
N20202489: C4.2 R6.1 Y1.2
N20224092: C2.2 D1.2(CATHODE) J1.1 L1.2
N20257999: J5.A5(CC1) R20.2
N20258001: J5.B5(CC2) R15.2
N20274526: D2.A(ANODE) R2.2
N20306435: J6.A5(CC1) R32.2
N20306436: J6.B5(CC2) R26.2
N20337202: C39.2 C40.1 L5.2 R35.1
N20337204: C47.2 J10.2 R35.2
N20337251: C40.2 C41.1 L6.2 R36.1
N20337259: C48.1 J10.3 R36.2
N20337346: C42.2 C43.1 L7.2 R37.1
N20337363: C49.2 J11.2 R37.2
N20337410: C43.2 C44.1 L8.2 R38.1
N20337418: C50.1 J11.3 R38.2
N20381027: D13.A(ANODE) R22.1
N20392329: D3.A(ANODE) R8.2
N20392898: D4.A(ANODE) R9.2
N20393445: D5.A(ANODE) R10.2
N20393873: D6.A(ANODE) R12.2
N20430471: C8.2 L2.1 U2.68(ANT)
N20434720: C52.1 L11.1 U2.67(POR)
N20435400: L4.1 U2.45(DCDCSW)
N20464812: C36.1 U7.1(OUTPUT)
N20464818: C38.1 R34.2 U7.2(GND) U7.3(GND)
N20464835: C45.1 J9.2
N20464868: C46.1 J9.3
N20464905: C37.1 R33.2 U7.4(VDD)
N20480616: TP7.1(TP) U1.12(DTR)
N20480626: TP4.1(TP) U1.11(DCD)
N20480630: TP6.1(TP) U1.10(ACT#)
N20480671: TP5.1(TP) U1.13(RTS)
N20480690: TP3.1(TP) U1.14(DSR)
N20480706: TP2.1(TP) U1.15(CTS)
N20480721: TP1.1(TP) U1.16(RI)
N20480861: J4.A5(CC1) R14.2
N20480863: J4.B5(CC2) R16.2
N20488900: J2.2 R3.1
N20488910: J2.4 R5.1
N20516342: L9.1 U2.69(VLINE)
N20517911: C10.1 U2.59(VMID)
N20535611: J3.9(1) R1.1

Not connected (* = marked no-connect by the designer): J3 10(2)*; J4 A8(SBU1)* B8(SBU2)*; J5 A8(SBU1)* B8(SBU2)*; J6 A8(SBU1)* B8(SBU2)*; J9 4*; J10 4*; J11 4*; U2 94(NC2) 95(NC3) 96(NC4); U6 4(NC)*

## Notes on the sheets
sheet 1
- Author
- Approved by
- zesheng
- Xiang
- Date
- Note
- REV1.0
- 2025/3/4
- Initial Version
- 1.Add a jumper to connect TL_VDD3DCDC to VDDO3
  2.Add a matching capacitor pad close to the chip side of the RF section
  3.PCB Layout: Place the chip close to the antenna connector; remove the through-hole antenna connector
  4.Change the power supply of AMIC to be from the GPIO port
  5.Eliminate jumper connections for all peripheral power supplies and replace them with 0Ω resistor short-circuits
  6.Change the PSRAM model to a 3.3V-powered version.
  7.Change the REF signal of the JTAG debug port to VDDO3
  8.Change the LED section to be directly driven by the GPIO port
  9.Add PC0 and PC1 nets to connector J1 for adapting to the key sub-board
  10.Modify the AMIC IO port configuration from PC0/PC1 to PC2/PC3
  11.Simplify the IO port configuration of the I3C module
  12.Modify the CTB section from the original PB0-PB7 to PC0-PC1 and PB2-PB7
  13.Remove the test points for USB (HS)
  14.Change the matching resistor of the CAN chip to 0805 package
- REV1.1
- 2025/5/09
- 1.Modify the board outline size to be consistent with that of other sold EVB versions;
  2.Adjust the capacitance value of C58 from 4.7uF to 10uF;
  3.Remove the entire PSRAM circuit;
  4.Modify the pin definition of JTAG connector to adapt to NXP JTAG;
  5.Remove the entire LIN circuit;
  6.Remove the entire CAN circuit;
  7.Remove the entire I3C circuit;
  8.Remove the entire LCD screen circuit;
  9.Remove the entire CTB circuit;
  10.Modify the chip model of UART circuit to CH343P for a higher communication rate;
  11.Modify the BEVK circuit to a module-based design.
- REV1.2
- 2025/7/25
- REV1.3
- 2025/12/02
- A special test version is modified to verify all harmonic-related test items during the FCC certification process.
   (This version is exclusively for FCC harmonic test verification, not for regular development, promotion or demonstration.)
- 1.Correct the partial silk screen marking errors existing in the V1.2
  version to ensure the accuracy and standardization of hardware markings;
  2.Adjust the connection mode of TL_VDDO3 with TL_VDDIO_AMS, TL_AVDD3 and TL_VDD3DCDC:
   replace the original jumper connection with 0Ω resistor connection, and add corresponding test points for this link;
  3.Adjust the connection mode of TL_VDD1P2 with TL_AVDD1P2, TL_DVDD1P2 and TL_VLINE:
  replace the original jumper connection with 0Ω resistor connection, and add corresponding test points for this link;
  4.Optimize the design of partial signal traces, adjust the relevant traces to the inner layer of PCB,
   and improve the stability of signal transmission and the EMC performance of hardware.
- REV1.4
- 2026/01/21
sheet 2
- ==MSPI&PI==
- ==PA==
- USB_DM(HS)
- USB_DP(HS)
- USB_DM
- ==VDDIOPE==
- USB_DP
- I3C1_SDA
- SWS
- ==PF==
- Crystal
- I3C2_SDA
- I3C1_SCL
- I3C2_SCL
- DMIC_CLK1
- DMIC_DAT
- ==PH==
- ==PG==
- ==PD==
- JTAG_TDI
- JTAG_TDO
- JTAG_TMS
- JTAG_TCK
- ==PC==
- AMIC
- AMIC
- 32K
- 32K
- BEVK
- ==CTB&PB==
- PB0
  + low, 4-wire jtag
  + high, 2-wire jtag
sheet 3
- LINE IN & AMIC
- SDM1
- SDMN1
- connect to PC1
- SDMP1
- connect to PC0
- SDM0
- connect to PC0
- SDMN0
- connect to PC1
- SDMP0
- DMIC
sheet 4
- ==MSPI&PI==
- ==PH==
- QSPI FLASH
- DUT USB0(HS)
- DUT USB1
- USB Type-C
- USB Type-C
- ==VDDIOPE==
- I3C1_SDA
- I3C2_SDA
- ==PF==
- 1.65V~3.6V
- I3C1_SCL
- I3C2_SCL
- DMIC_CLK1
- DMIC_DAT
- DMIC_CLK2
- USB转UART
- ==PA==
- SWS
- USB Type-C
- ==PG==
- USB_DM(HS)
- JTAG_TMS
- JTAG_TCK
- USB_DP(HS)
- JTAG_TDO
- USB_DM
- JTAG_TDI
- USB_DP
- SWS
- ==PD==
- LED
- KEY
- JTAG option
- JTAG_TDI
- JTAG_TDO
- JTAG_TMS
- JTAG_TCK
- PIN1 to 2: JTAG, 4 wire
- PIN3 to 4: JTAG, 2 wire
- ==PC==
- AMIC
- AMIC
- 32K
- 32K
- ==CTB&PB==
- PB0
  + low, 4-wire jtag
  + high, 2-wire jtag
- IR
sheet 5
- BOTTOM
- BOTTOM
